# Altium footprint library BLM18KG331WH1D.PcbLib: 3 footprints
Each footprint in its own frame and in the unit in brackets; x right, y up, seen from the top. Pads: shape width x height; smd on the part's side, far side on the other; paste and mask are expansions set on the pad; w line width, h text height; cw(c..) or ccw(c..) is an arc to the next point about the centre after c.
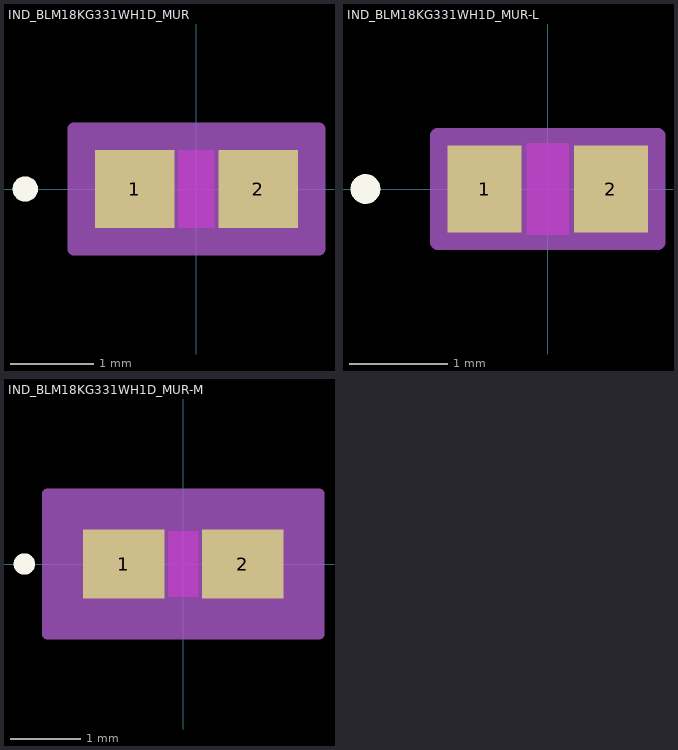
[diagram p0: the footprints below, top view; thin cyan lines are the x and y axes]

## IND_BLM18KG331WH1D_MUR [mil]
pads (2):
  rect 37.78x37 smd paste+0 mask+0: 1(-29.39,0) 2(29.39,0)
Top Layer keep-out:
  region: -8.5,-16.5 -8.5,16.5 8.5,16.5 8.5,-16.5
Top Overlay:
  circle w6: c-81.28,0 r3
  text ".Designator" at -137.5,-25 h50
Keep-Out Layer:
  region: -8.5,-18.5 -8.5,18.5 8.5,18.5 8.5,-18.5
Mechanical 13:
  circle w1: c-24.39,0 r3
  lines w1: -34.5,-18.5 -34.5,18.5 ; -34.5,-18.5 -10.5,-18.5 -10.5,18.5 -34.5,18.5 ; -34.5,-18.5 34.5,-18.5 ; -34.5,-18.5 -34.5,18.5 ; -34.5,18.5 34.5,18.5 ; 34.5,-18.5 10.5,-18.5 10.5,18.5 34.5,18.5 ; 34.5,-18.5 34.5,18.5 ; 34.5,-18.5 34.5,18.5
  text ".Designator" at -137.5,-25 h50
Mechanical 15:
  region: 58.28,-28.5 -58.28,-28.5 -58.28,28.5 58.28,28.5
  lines w6: -58.28,-28.5 -58.28,28.5 58.28,28.5 58.28,-28.5 -58.28,-28.5
3D body "IND_BLM18KG331WH1D_MUR.step": height 37.01, standoff 0, extent -34.49,-18.5 34.49,18.5

## IND_BLM18KG331WH1D_MUR-L [mil]
pads (2):
  rect 29.91x35.03 smd paste+0 mask+0: 1(-25.45,0) 2(25.45,0)
Top Layer keep-out:
  region: -8.5,-16.5 -8.5,16.5 8.5,16.5 8.5,-16.5
Top Overlay:
  circle w6: c-73.41,0 r3
  text ".Designator" at -137.5,-25 h50
Keep-Out Layer:
  region: -8.5,-18.5 -8.5,18.5 8.5,18.5 8.5,-18.5
Mechanical 13:
  circle w1: c-20.45,0 r3
  lines w1: -34.5,-18.5 -34.5,18.5 ; -34.5,-18.5 -10.5,-18.5 -10.5,18.5 -34.5,18.5 ; -34.5,-18.5 34.5,-18.5 ; -34.5,-18.5 -34.5,18.5 ; -34.5,18.5 34.5,18.5 ; 34.5,-18.5 10.5,-18.5 10.5,18.5 34.5,18.5 ; 34.5,-18.5 34.5,18.5 ; 34.5,-18.5 34.5,18.5
  text ".Designator" at -137.5,-25 h50
Mechanical 15:
  region: 44.41,-21.52 -44.41,-21.52 -44.41,21.52 44.41,21.52
  lines w6: -44.41,-21.52 -44.41,21.52 44.41,21.52 44.41,-21.52 -44.41,-21.52
3D body "IND_BLM18KG331WH1D_MUR.step": height 37.01, standoff 0, extent -34.49,-18.5 34.49,18.5

## IND_BLM18KG331WH1D_MUR-M [mil]
pads (2):
  rect 45.65x38.97 smd paste+0 mask+0: 1(-33.33,0) 2(33.33,0)
Top Layer keep-out:
  region: -8.5,-16.5 -8.5,16.5 8.5,16.5 8.5,-16.5
Top Overlay:
  circle w6: c-89.15,0 r3
  text ".Designator" at -137.5,-25 h50
Keep-Out Layer:
  region: -8.5,-18.5 -8.5,18.5 8.5,18.5 8.5,-18.5
Mechanical 13:
  circle w1: c-28.33,0 r3
  lines w1: -34.5,-18.5 -34.5,18.5 ; -34.5,-18.5 -10.5,-18.5 -10.5,18.5 -34.5,18.5 ; -34.5,-18.5 34.5,-18.5 ; -34.5,-18.5 -34.5,18.5 ; -34.5,18.5 34.5,18.5 ; 34.5,-18.5 10.5,-18.5 10.5,18.5 34.5,18.5 ; 34.5,-18.5 34.5,18.5 ; 34.5,-18.5 34.5,18.5
  text ".Designator" at -137.5,-25 h50
Mechanical 15:
  region: 76.15,-39.48 -76.15,-39.48 -76.15,39.48 76.15,39.48
  lines w6: -76.15,-39.48 -76.15,39.48 76.15,39.48 76.15,-39.48 -76.15,-39.48
3D body "IND_BLM18KG331WH1D_MUR.step": height 37.01, standoff 0, extent -34.49,-18.5 34.49,18.5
